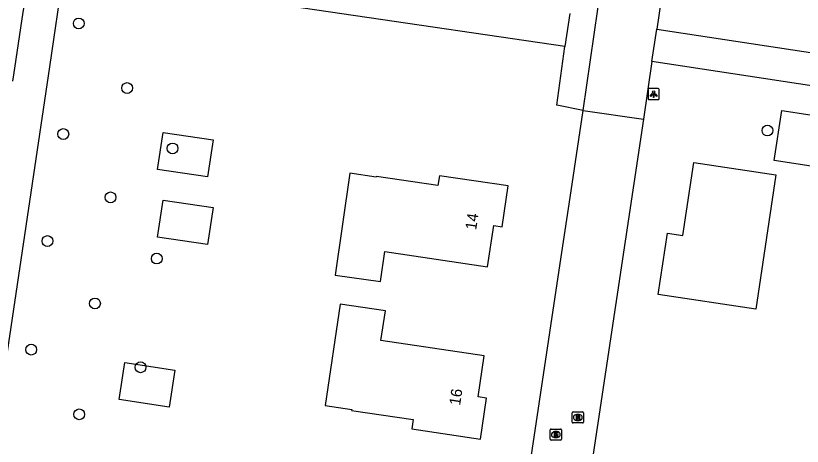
# Model space of a CAD drawing. Extents: x 164150 to 165261, y 382513 to 383432.
# Drawn here: x 164601.9 to 164672.8, y 382971.2 to 383010 of the extents above; entities that cross this region are included whole.
import ezdxf

# ---------------------------------------------------------------- set-up
doc = ezdxf.new("R2010")
doc.units = 0
for name, color, linetype in [('IMGEO_Boom', 7, 'Continuous'), ('IMGEO_Fietspad_gesloten', 7, 'Continuous'), ('IMGEO_Lichtpunt', 7, 'Continuous'), ('IMGEO_Pand', 7, 'Continuous'), ('IMGEO_Pand_nummerreeks', 7, 'Continuous'), ('IMGEO_Pand_vergunning_verleend', 7, 'Continuous'), ('IMGEO_Rijbaan_lokaal_gesloten', 7, 'Continuous'), ('IMGEO_Rijbaan_lokaal_open', 7, 'Continuous'), ('IMGEO_Rioolput', 7, 'Continuous'), ('IMGEO_Voetpad_open', 7, 'Continuous')]:
    doc.layers.add(name, color=color, linetype=linetype)

msp = doc.modelspace()

# ---------------------------------------------------------------- linework, layer by layer
at = {"layer": 'IMGEO_Boom'}
for centre in [(164607.602, 383009.313), (164611.961, 383003.491), (164669.686, 382999.661), (164606.211, 382999.345), (164616.057, 382998.047), (164610.467, 382993.634), (164604.783, 382989.699), (164614.635, 382988.122), (164609.06, 382984.073), (164603.316, 382979.911), (164613.172, 382978.323), (164607.645, 382974.081)]:
    msp.add_circle(centre, 0.489, dxfattribs=at)
at = {"layer": 'IMGEO_Fietspad_gesloten'}
for points in [[(164601.66, 383004.124), (164601.744, 383004.692), (164602.579, 383010.326), (164603.253, 383014.289)], [(164606.207, 383013.843), (164604.952, 383005.406), (164583.055, 382858.156), (164580.335, 382839.876)], [(164651.419, 383007.225), (164611.224, 383013.148), (164606.207, 383013.843)], [(164651.876, 383010.215), (164651.419, 383007.225)], [(164659.708, 383008.804), (164765.127, 382992.769), (164849.159, 382980.044), (164853.349, 382979.402)], [(164852.653, 382976.484), (164848.685, 382977.103), (164764.64, 382989.85), (164659.275, 383005.882)]]:
    msp.add_lwpolyline(points, dxfattribs=at)
at = {"layer": 'IMGEO_Lichtpunt'}
for p, q in [((164658.931, 383003.345), (164658.931, 383002.538)), ((164658.931, 383003.345), (164658.931, 383002.538)), ((164659.833, 383003.44), (164659.025, 383003.44)), ((164659.833, 383003.44), (164659.025, 383003.44)), ((164659.927, 383002.538), (164659.927, 383003.345)), ((164659.927, 383002.538), (164659.927, 383003.345)), ((164659.025, 383002.444), (164659.833, 383002.444)), ((164659.025, 383002.444), (164659.833, 383002.444))]:
    msp.add_line(p, q, dxfattribs=at)
for points in [[(164659.305, 383003.009), (164659.344, 383002.981), (164659.156, 383002.719), (164659.118, 383002.746), (164659.305, 383003.009)], [(164659.407, 383002.961), (164659.454, 383002.961), (164659.454, 383002.639), (164659.407, 383002.639), (164659.407, 383002.961)], [(164659.517, 383002.981), (164659.555, 383003.008), (164659.742, 383002.746), (164659.703, 383002.718), (164659.517, 383002.981)]]:
    msp.add_lwpolyline(points, dxfattribs=at)
msp.add_circle((164659.43, 383003.143), 0.0994, dxfattribs=at)
for centre, start, end in [((164659.025, 383003.345), 90, 180), ((164659.025, 383003.345), 90, 180), ((164659.833, 383003.345), 0, 90), ((164659.833, 383003.345), 0, 90), ((164659.025, 383002.538), 180, 270), ((164659.025, 383002.538), 180, 270), ((164659.833, 383002.538), 270, 0), ((164659.833, 383002.538), 270, 360)]:
    msp.add_arc(centre, 0.0946, start, end, dxfattribs=at)
at = {"layer": 'IMGEO_Pand'}
for points in [[(164646.304, 382994.68), (164640.107, 382995.58), (164639.974, 382994.716), (164634.437, 382995.517), (164634.426, 382995.445), (164632.029, 382995.804), (164630.707, 382986.634), (164634.798, 382986.068), (164635.187, 382988.764), (164644.462, 382987.389), (164645.008, 382991.1), (164645.761, 382990.996), (164646.304, 382994.68)], [(164634.842, 382980.742), (164635.24, 382983.412), (164631.153, 382984.005), (164629.82, 382974.864), (164632.209, 382974.508), (164632.199, 382974.437), (164637.76, 382973.617), (164637.635, 382972.77), (164643.826, 382971.849), (164644.373, 382975.545), (164643.615, 382975.658), (164644.162, 382979.358), (164634.842, 382980.742)]]:
    msp.add_lwpolyline(points, dxfattribs=at)
at = {"layer": 'IMGEO_Pand_vergunning_verleend'}
for points in [[(164670.299, 382996.955), (164670.97, 383001.461), (164674.305, 383000.965), (164673.635, 382996.458), (164670.299, 382996.955)], [(164614.702, 382996.161), (164615.198, 382999.497), (164619.705, 382998.826), (164619.208, 382995.491), (164614.702, 382996.161)], [(164659.838, 382984.873), (164660.67, 382990.414), (164662.062, 382990.205), (164663.05, 382996.782), (164670.444, 382995.672), (164668.624, 382983.554), (164659.838, 382984.873)], [(164614.702, 382990.049), (164615.198, 382993.384), (164619.705, 382992.714), (164619.208, 382989.378), (164614.702, 382990.049)], [(164611.255, 382975.412), (164611.751, 382978.748), (164616.258, 382978.077), (164615.761, 382974.742), (164611.255, 382975.412)]]:
    msp.add_lwpolyline(points, dxfattribs=at)
at = {"layer": 'IMGEO_Rijbaan_lokaal_gesloten'}
for points in [[(164631.941, 382858.849), (164645.496, 382950.967), (164651.008, 382987.673), (164651.902, 382993.63), (164653.078, 383001.462)], [(164653.078, 383001.462), (164658.504, 383000.69)], [(164658.504, 383000.69), (164650.933, 382950.305), (164641.67, 382887.255), (164640.801, 382881.34), (164637.731, 382860.442), (164636.909, 382854.849), (164636.824, 382854.453), (164636.636, 382853.576)]]:
    msp.add_lwpolyline(points, dxfattribs=at)
at = {"layer": 'IMGEO_Rijbaan_lokaal_open'}
for points in [[(164653.078, 383001.462), (164657.714, 383033.452)], [(164660.073, 383011.264), (164659.708, 383008.804)], [(164659.275, 383005.882), (164659.708, 383008.804)], [(164659.275, 383005.882), (164658.504, 383000.69)]]:
    msp.add_lwpolyline(points, dxfattribs=at)
at = {"layer": 'IMGEO_Rioolput'}
for p, q in [((164652.092, 382973.375), (164652.092, 382974.227)), ((164652.167, 382974.301), (164653.019, 382974.301)), ((164652.58, 382974.081), (164652.605, 382974.081)), ((164653.093, 382974.227), (164653.093, 382973.375)), ((164653.019, 382973.301), (164652.167, 382973.301)), ((164652.603, 382973.521), (164652.578, 382973.521)), ((164650.111, 382971.832), (164650.111, 382972.684)), ((164650.186, 382972.758), (164651.038, 382972.758)), ((164650.599, 382972.538), (164650.624, 382972.538)), ((164651.112, 382972.684), (164651.112, 382971.832)), ((164651.038, 382971.758), (164650.186, 382971.758)), ((164650.622, 382971.978), (164650.597, 382971.978))]:
    msp.add_line(p, q, dxfattribs=at)
for points in [[(164652.092, 382973.375), (164652.092, 382974.227)], [(164652.167, 382974.301), (164653.019, 382974.301)], [(164652.681, 382973.999), (164652.429, 382974.001), (164652.429, 382973.601)], [(164652.607, 382973.92), (164652.553, 382973.92), (164652.553, 382973.839)], [(164652.553, 382973.839), (164652.605, 382973.839)], [(164653.093, 382974.227), (164653.093, 382973.375)], [(164653.019, 382973.301), (164652.167, 382973.301)], [(164652.429, 382973.601), (164652.553, 382973.601), (164652.553, 382973.763), (164652.564, 382973.763)], [(164652.611, 382973.734), (164652.682, 382973.601), (164652.822, 382973.601), (164652.757, 382973.727)], [(164650.111, 382971.832), (164650.111, 382972.684)], [(164650.186, 382972.758), (164651.038, 382972.758)], [(164650.7, 382972.456), (164650.448, 382972.458), (164650.448, 382972.058)], [(164651.112, 382972.684), (164651.112, 382971.832)], [(164651.038, 382971.758), (164650.186, 382971.758)], [(164650.448, 382972.058), (164650.572, 382972.058), (164650.572, 382972.22), (164650.583, 382972.22)], [(164650.626, 382972.377), (164650.572, 382972.377), (164650.572, 382972.296)], [(164650.572, 382972.296), (164650.624, 382972.296)], [(164650.63, 382972.191), (164650.701, 382972.058), (164650.841, 382972.058), (164650.776, 382972.184)]]:
    msp.add_lwpolyline(points, dxfattribs=at)
for centre, radius, start, end in [((164652.169, 382974.225), 0.0765, 91.55205, 178.44795), ((164652.169, 382974.225), 0.0765, 91.55205, 178.44795), ((164652.589, 382974.028), 0.19, 274.7715, 282.96867), ((164652.613, 382973.824), 0.0964, 77.00612, 93.18647), ((164652.627, 382973.881), 0.0378, 276.66336, 79.67722), ((164652.68, 382973.889), 0.109, 350.36119, 89.41601), ((164652.678, 382973.889), 0.112, 277.58423, 350.98172), ((164653.017, 382974.225), 0.0765, 1.55205, 88.44795), ((164653.017, 382974.225), 0.0765, 1.55205, 88.44795), ((164652.169, 382973.377), 0.0765, 181.55205, 268.44795), ((164652.169, 382973.377), 0.0765, 181.55205, 268.44795), ((164652.563, 382973.71), 0.0533, 26.02933, 88.69889), ((164652.662, 382973.674), 0.108, 29.51342, 73.79051), ((164653.017, 382973.377), 0.0765, 271.55205, 358.44795), ((164653.017, 382973.377), 0.0765, 271.55205, 358.44795), ((164650.188, 382972.682), 0.0765, 91.55205, 178.44795), ((164650.188, 382972.682), 0.0765, 91.55205, 178.44795), ((164650.699, 382972.346), 0.109, 350.36119, 89.41601), ((164651.036, 382972.682), 0.0765, 1.55205, 88.44795), ((164651.036, 382972.682), 0.0765, 1.55205, 88.44795), ((164650.188, 382971.834), 0.0765, 181.55205, 268.44795), ((164650.188, 382971.834), 0.0765, 181.55205, 268.44795), ((164650.582, 382972.167), 0.0533, 26.02933, 88.69889), ((164650.608, 382972.485), 0.19, 274.7715, 282.96867), ((164650.632, 382972.281), 0.0964, 77.00612, 93.18647), ((164650.646, 382972.338), 0.0378, 276.66336, 79.67722), ((164650.697, 382972.346), 0.112, 277.58423, 350.98172), ((164650.681, 382972.131), 0.108, 29.51342, 73.79051), ((164651.036, 382971.834), 0.0765, 271.55205, 358.44795), ((164651.036, 382971.834), 0.0765, 271.55205, 358.44795)]:
    msp.add_arc(centre, radius, start, end, dxfattribs=at)
for centre, major_axis, ratio, start_param, end_param in [((164652.579, 382973.801), (-0.387, 0.002), 0.722429, 4.712389, 7.853982), ((164652.604, 382973.801), (-0.39, 0.002), 0.717154, 1.570796, 4.712389), ((164650.598, 382972.258), (-0.387, 0.002), 0.722429, 4.712389, 7.853982), ((164650.623, 382972.258), (-0.39, 0.002), 0.717154, 1.570796, 4.712389)]:
    msp.add_ellipse(centre, major_axis=major_axis, ratio=ratio, start_param=start_param, end_param=end_param, dxfattribs=at)
at = {"layer": 'IMGEO_Voetpad_open'}
msp.add_lwpolyline([(164653.078, 383001.462), (164650.705, 383001.947), (164651.419, 383007.225)], dxfattribs=at)

# ---------------------------------------------------------------- texts
at = {"layer": 'IMGEO_Pand_nummerreeks'}
for s, rotation, p in [('14', 81.6293, (164643.426, 382990.658)), ('16', 81.58919, (164641.978, 382974.841))]:
    msp.add_text(s, height=1, rotation=rotation, dxfattribs=at).set_placement(p)

doc.saveas('drawing.dxf')
